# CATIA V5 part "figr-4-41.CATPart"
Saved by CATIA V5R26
Part number: Part1
Bounding box of the stored display mesh (mm): x -89.975 to 89.975, y -89.975 to 89.975, z 0 to 190
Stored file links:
  D:\_Deepak\CATIA\CATIA V5-6R2016_Deepak\Resources\Part files\Partfiles\c04_catia_v5_6r2016_prt\figr-4-41.CATPart
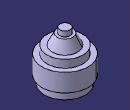
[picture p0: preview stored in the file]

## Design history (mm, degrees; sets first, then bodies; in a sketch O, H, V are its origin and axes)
Set1
  Line1 "Y Axis": stored without definition
  Line2 "Y Axis": stored without definition
  Line3 "X Axis": stored without definition
  Line4 "Z Axis": stored without definition
Body1 (main body)
  Sketch1 on yz-plane, origin (0, 0, 0), H (0, 1, 0), V (0, 0, 1)
    line L1 (0, 0) -> (80, 0)
    line L2 (80, 0) -> (80, 30)
    line L3 (80, 30) -> (90, 30)
    line L4 (90, 30) -> (90, 100)
    line L5 (90, 100) -> (70, 100)
    line L6 (70, 100) -> (70, 130)
    line L7 (70, 130) -> (50, 130)
    line L8 (50, 130) -> (30, 170)
    line L9 (30, 170) -> (20, 170)
    line L10 (20, 170) -> (20, 190)
    line L11 (20, 190) -> (0, 190)
    point P11 (0, 190)
    line L12 (0, 190) -> (0, 0)
    axis line L13 (0, -40) -> (0, 230)
    point P12 (0, -40)
    point P13 (0, 230)
    horizontal: L1 H, L3 H, L5 H, L7 H, L9 H, L11 H
    vertical: L2 V, L4 V, L6 V, L10 V, L12 V, L13 V
    coincidence: P11 V, P12 V, P13 L8
  Shaft1: profile Sketch1, axis Sketch1.L13, angle 360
